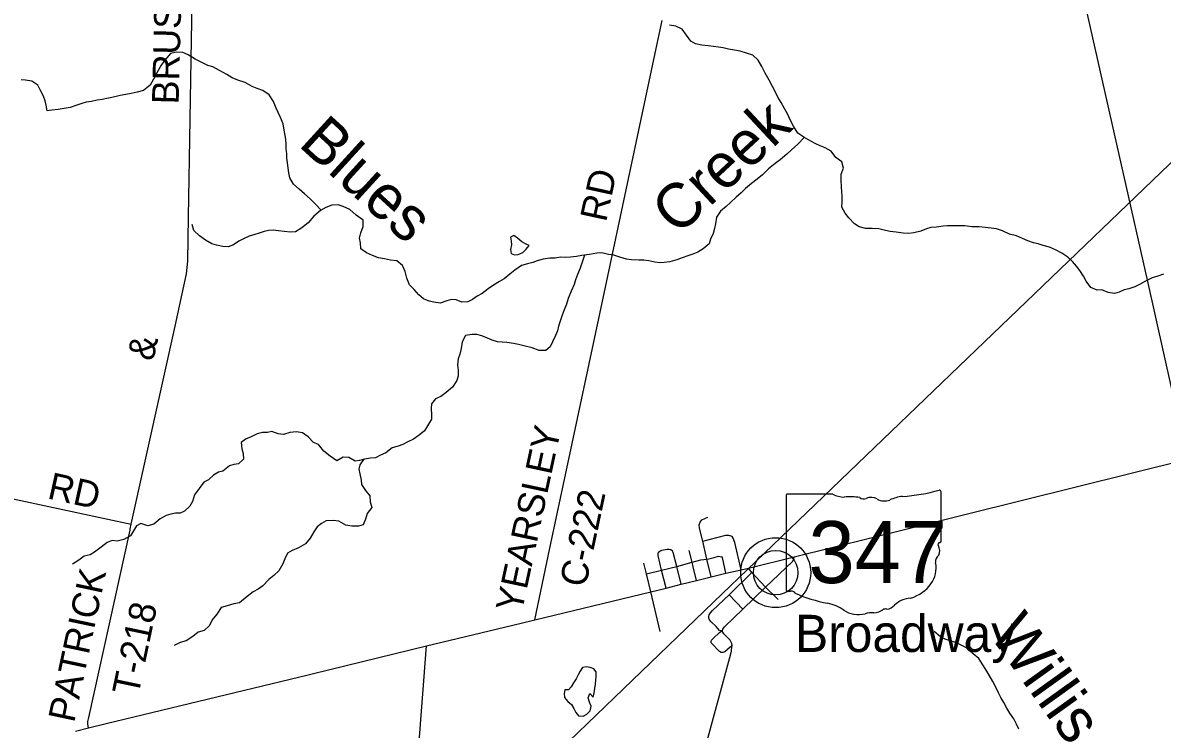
# Model space of a CAD drawing. Extents: x 0 to 34, y 0 to 22.
# Drawn here: x 5.454 to 6.665, y 16.008 to 16.759 of the extents above; entities that cross this region are included whole.
import ezdxf

# ---------------------------------------------------------------- set-up
doc = ezdxf.new("R2010")
doc.units = 0
for name, color, linetype in [('GM_X_County_Road', 7, 'Continuous'), ('GM_X_County_Road_Text', 7, 'Continuous'), ('GM_X_Minor_Lake', 7, 'Continuous'), ('GM_X_Minor_River', 7, 'Continuous'), ('GM_X_Minor_River_Text', 7, 'Continuous'), ('GM_X_Rail_Line', 7, 'Continuous'), ('GM_X_State_Location', 7, 'Continuous'), ('GM_X_State_Route', 7, 'Continuous'), ('GM_X_State_Shield', 7, 'Continuous'), ('GM_X_Township_Road', 7, 'Continuous'), ('GM_X_Township_Road_Text', 7, 'Continuous'), ('GM_X_Unincorporated', 7, 'Continuous'), ('GM_X_Unincorporated_Location', 7, 'Continuous'), ('GM_X_Unincorporated_Text', 7, 'Continuous')]:
    doc.layers.add(name, color=color, linetype=linetype)

msp = doc.modelspace()

# ---------------------------------------------------------------- linework, layer by layer
at = {"layer": 'GM_X_County_Road'}
for points in [[(5.9984, 16.124), (6.0142, 16.2003), (6.0675, 16.4491), (6.1282, 16.7363), (6.1336, 16.7611)], [(5.8932, 15.2994), (5.8674, 15.5635), (5.855, 15.6874), (5.8535, 15.703), (5.8532, 15.7217), (5.8547, 15.7358), (5.8584, 15.7865), (5.8627, 15.8321), (5.8703, 15.9318), (5.8747, 15.985), (5.8831, 16.0962)]]:
    msp.add_lwpolyline(points, dxfattribs=at)
at = {"layer": 'GM_X_Minor_Lake'}
for points in [[(5.989, 16.5234), (5.9883, 16.5237), (5.9846, 16.5258), (5.98, 16.5295), (5.9761, 16.5325), (5.9726, 16.5306), (5.9732, 16.5264), (5.9736, 16.5227), (5.9726, 16.5177), (5.9732, 16.5134)], [(5.9732, 16.5134), (5.9767, 16.512), (5.9807, 16.5124), (5.9855, 16.5145), (5.9893, 16.518), (5.9923, 16.522), (5.989, 16.5234)], [(6.058, 16.0303), (6.0584, 16.0322), (6.0565, 16.0364), (6.0551, 16.0411), (6.0568, 16.0455), (6.0602, 16.0417), (6.0613, 16.0462), (6.0627, 16.0555), (6.0631, 16.0599), (6.0635, 16.0641), (6.0635, 16.0686), (6.061, 16.072), (6.0573, 16.0732), (6.0531, 16.074), (6.0489, 16.0734), (6.0466, 16.0694), (6.0445, 16.0655), (6.0424, 16.0613), (6.0396, 16.0569), (6.0371, 16.0526), (6.0341, 16.0496), (6.0301, 16.0496)], [(6.0301, 16.0496), (6.0297, 16.0458), (6.03, 16.0414), (6.0334, 16.037), (6.0374, 16.0338), (6.0399, 16.0298), (6.0419, 16.0256), (6.0449, 16.022), (6.0497, 16.0216), (6.0538, 16.0237), (6.0573, 16.0273), (6.058, 16.0303)]]:
    msp.add_lwpolyline(points, dxfattribs=at)
at = {"layer": 'GM_X_Minor_River'}
for points in [[(6.3239, 16.5912), (6.3239, 16.5978), (6.3264, 16.6041), (6.3247, 16.6107), (6.3183, 16.6155), (6.3134, 16.6223), (6.3068, 16.6258), (6.3017, 16.6279), (6.2968, 16.63), (6.2917, 16.6328), (6.2843, 16.6369), (6.2779, 16.6414), (6.2732, 16.6488), (6.2696, 16.6555), (6.2668, 16.6618), (6.2641, 16.6669), (6.2602, 16.6739), (6.2566, 16.6794), (6.2538, 16.6857), (6.251, 16.691), (6.2474, 16.6977), (6.2433, 16.7049), (6.2397, 16.7121), (6.2357, 16.7188), (6.2301, 16.7243), (6.2233, 16.7262), (6.2166, 16.7283), (6.2104, 16.7295), (6.204, 16.7307), (6.1985, 16.732), (6.1934, 16.7328), (6.1881, 16.7334), (6.1824, 16.7342), (6.1758, 16.7349), (6.1691, 16.7363), (6.164, 16.7392), (6.1595, 16.7454), (6.1548, 16.7519), (6.1482, 16.7551), (6.1414, 16.7561)], [(5.7713, 16.5594), (5.7648, 16.5662), (5.7597, 16.5715), (5.7535, 16.5769), (5.748, 16.5818), (5.742, 16.5872), (5.738, 16.5938), (5.7369, 16.5991), (5.7354, 16.6098), (5.7349, 16.6147), (5.7347, 16.6194), (5.7343, 16.6251), (5.7342, 16.6304), (5.7336, 16.6369), (5.7321, 16.6443), (5.7308, 16.6513), (5.728, 16.6581), (5.7256, 16.6631), (5.7235, 16.668), (5.7207, 16.6749), (5.716, 16.6821), (5.7094, 16.6867), (5.7033, 16.6886), (5.6979, 16.6909), (5.6905, 16.6951), (5.6827, 16.6977), (5.6769, 16.7002), (5.671, 16.7035), (5.6634, 16.7079), (5.6561, 16.7117), (5.651, 16.7132), (5.6438, 16.7166), (5.6374, 16.7201), (5.63, 16.7246), (5.6245, 16.7269), (5.6177, 16.7273), (5.6114, 16.726), (5.6053, 16.7188), (5.6015, 16.7134), (5.5966, 16.7054), (5.5931, 16.6988), (5.5895, 16.6922), (5.5825, 16.6867), (5.5758, 16.6848), (5.5694, 16.6833), (5.5637, 16.6822), (5.5576, 16.6813), (5.5521, 16.6799), (5.5385, 16.677), (5.5334, 16.6764), (5.5273, 16.6751), (5.5218, 16.6742), (5.5171, 16.6728), (5.5106, 16.6706), (5.5047, 16.6687), (5.4981, 16.6674), (5.4919, 16.6665), (5.485, 16.6657), (5.4803, 16.665), (5.4792, 16.6709), (5.4781, 16.6756), (5.4764, 16.6806), (5.4728, 16.6874), (5.4704, 16.6923), (5.4638, 16.6967), (5.4573, 16.6975), (5.4524, 16.6979)], [(6.2846, 16.6367), (6.2778, 16.6297), (6.271, 16.6236), (6.2662, 16.6189), (6.2592, 16.6131), (6.2539, 16.6089), (6.2467, 16.6032), (6.2402, 16.597), (6.2345, 16.5925), (6.2286, 16.5879), (6.2223, 16.5825), (6.2176, 16.5777), (6.2123, 16.5734), (6.2064, 16.5677), (6.2016, 16.5634), (6.1955, 16.5583), (6.1915, 16.552), (6.1905, 16.5448), (6.1892, 16.5399), (6.1877, 16.5348), (6.1852, 16.5285), (6.1835, 16.5238), (6.1774, 16.5183), (6.1717, 16.5149), (6.1662, 16.5127), (6.1609, 16.5108), (6.155, 16.5087), (6.1493, 16.5065), (6.1419, 16.5046), (6.1358, 16.5037), (6.1311, 16.5035), (6.126, 16.5041), (6.1194, 16.5056), (6.1141, 16.5062), (6.1088, 16.5062), (6.1012, 16.5068), (6.0957, 16.5074), (6.0887, 16.5095), (6.0823, 16.5115), (6.0768, 16.5124), (6.0696, 16.514), (6.0643, 16.5136), (6.0565, 16.5123), (6.0485, 16.5114), (6.0425, 16.5101), (6.0362, 16.5095), (6.0311, 16.5092), (6.0258, 16.5094), (6.0199, 16.5085), (6.0144, 16.5085), (6.0072, 16.5074), (6.001, 16.5055), (5.9962, 16.5038), (5.9905, 16.5025), (5.9841, 16.5006), (5.9771, 16.4957), (5.9719, 16.4915), (5.9658, 16.4864), (5.9607, 16.4836), (5.9545, 16.4797), (5.9489, 16.4759), (5.9425, 16.471), (5.9372, 16.468), (5.932, 16.4644), (5.9271, 16.4621), (5.9207, 16.4616), (5.9148, 16.4641), (5.9099, 16.4644), (5.905, 16.4631), (5.8979, 16.4607), (5.8911, 16.4615), (5.8862, 16.4628), (5.8801, 16.4653), (5.8752, 16.4695), (5.87, 16.4752), (5.8651, 16.4802), (5.8624, 16.487), (5.8607, 16.4942), (5.8579, 16.5007), (5.8519, 16.5056), (5.8451, 16.5064), (5.8385, 16.5076), (5.8322, 16.5087), (5.8258, 16.5112), (5.8195, 16.5139), (5.8135, 16.5185), (5.8131, 16.5247), (5.8122, 16.5296), (5.8136, 16.5355), (5.816, 16.5422), (5.8161, 16.5488), (5.8087, 16.5541), (5.8017, 16.56), (5.7947, 16.5635), (5.7894, 16.5652), (5.7828, 16.5646), (5.7762, 16.5624), (5.7706, 16.559), (5.7636, 16.5529), (5.7575, 16.5461), (5.7507, 16.5407)], [(6.6664, 16.4915), (6.6603, 16.4894), (6.6544, 16.4875), (6.6474, 16.4838), (6.6408, 16.4804), (6.636, 16.4779), (6.6296, 16.4757), (6.6246, 16.4746), (6.6193, 16.4723), (6.6142, 16.471), (6.6076, 16.472), (6.601, 16.4748), (6.5958, 16.4745), (6.5892, 16.4774), (6.5843, 16.484), (6.5815, 16.4893), (6.5775, 16.4952), (6.5738, 16.5), (6.5698, 16.5047), (6.5649, 16.5093), (6.5585, 16.5137), (6.5517, 16.5171), (6.5452, 16.52), (6.5384, 16.5219), (6.5331, 16.5235), (6.5282, 16.5246), (6.5224, 16.5269), (6.5167, 16.5292), (6.5102, 16.5321), (6.5027, 16.534), (6.4953, 16.5374), (6.4889, 16.5396), (6.4834, 16.5403), (6.4768, 16.5411), (6.4701, 16.5417), (6.4627, 16.5417), (6.4552, 16.5427), (6.437, 16.5428), (6.4321, 16.5424), (6.4252, 16.5415), (6.4192, 16.541), (6.4144, 16.5396), (6.4087, 16.5372), (6.401, 16.5355), (6.3958, 16.5346), (6.3896, 16.535), (6.3824, 16.5362), (6.376, 16.5366), (6.3709, 16.5377), (6.3638, 16.5395), (6.3567, 16.5399), (6.3496, 16.5399), (6.343, 16.5418), (6.3379, 16.5449), (6.3321, 16.5513), (6.3283, 16.5563), (6.3247, 16.5625), (6.3248, 16.5686), (6.325, 16.5739), (6.3246, 16.579), (6.3241, 16.5844), (6.3239, 16.5912)], [(5.7507, 16.5407), (5.744, 16.5365), (5.7389, 16.536), (5.7319, 16.5369), (5.7261, 16.5375), (5.7204, 16.5381), (5.7154, 16.5377), (5.7107, 16.5366), (5.7056, 16.5351), (5.7008, 16.5334), (5.695, 16.5319), (5.6895, 16.5293), (5.684, 16.5263), (5.6781, 16.5225), (5.6726, 16.5204), (5.6669, 16.5208), (5.6603, 16.5222), (5.6552, 16.5235), (5.6483, 16.5277), (5.6419, 16.5321), (5.6361, 16.5378), (5.6344, 16.5441)], [(6.0513, 16.5117), (6.0485, 16.503), (6.0464, 16.4979), (6.0437, 16.4911), (6.0416, 16.4854), (6.0401, 16.4803), (6.037, 16.4733), (6.0338, 16.4655), (6.0319, 16.4595), (6.0296, 16.4534), (6.0273, 16.4477), (6.0255, 16.4424), (6.0236, 16.4362), (6.0223, 16.4312), (6.0205, 16.4263), (6.0173, 16.4193), (6.0146, 16.414), (6.0099, 16.4104), (6.0031, 16.4101), (5.9957, 16.4131), (5.9868, 16.4151), (5.9811, 16.4166), (5.9756, 16.4178), (5.9688, 16.4189), (5.9637, 16.4191), (5.9586, 16.4195), (5.9529, 16.4212), (5.948, 16.4232), (5.9419, 16.426), (5.9366, 16.4274), (5.9315, 16.4272), (5.9247, 16.4263), (5.9211, 16.4193), (5.9201, 16.4124), (5.9186, 16.4062), (5.917, 16.4015), (5.9162, 16.395), (5.9168, 16.3895), (5.9168, 16.3834), (5.9156, 16.3783), (5.9108, 16.3713), (5.9042, 16.3656), (5.8985, 16.3615), (5.8928, 16.3589), (5.8886, 16.3536), (5.8882, 16.3486), (5.8886, 16.342), (5.8886, 16.3371), (5.8845, 16.3301), (5.8811, 16.3248), (5.8754, 16.3202), (5.8695, 16.3159), (5.8636, 16.3131), (5.8583, 16.3102), (5.8532, 16.3085), (5.8468, 16.3067), (5.8399, 16.3016), (5.8344, 16.2991), (5.8291, 16.2963), (5.8238, 16.2957), (5.8174, 16.2946), (5.8122, 16.2935), (5.8075, 16.2926), (5.8009, 16.2966), (5.7948, 16.297), (5.788, 16.2928), (5.7808, 16.2978), (5.7742, 16.3031), (5.7684, 16.3103), (5.7633, 16.3124), (5.7576, 16.3185), (5.7515, 16.3229), (5.7453, 16.3239), (5.7381, 16.3231), (5.7313, 16.3211), (5.7256, 16.3215), (5.719, 16.324), (5.7142, 16.323), (5.7091, 16.323), (5.7032, 16.3217), (5.6964, 16.3182), (5.6917, 16.3165), (5.6863, 16.3123), (5.6869, 16.3059), (5.6886, 16.3009), (5.6889, 16.2947), (5.6834, 16.2899), (5.6787, 16.2892), (5.6739, 16.2877), (5.6669, 16.282), (5.6622, 16.2809), (5.657, 16.2777), (5.6515, 16.2728), (5.6468, 16.2703), (5.6418, 16.2635), (5.6367, 16.2567), (5.6346, 16.2497), (5.6319, 16.2448), (5.6262, 16.2395), (5.6215, 16.2372), (5.6165, 16.2372)], [(5.8162, 16.2944), (5.8124, 16.2888), (5.8114, 16.284), (5.8126, 16.2793), (5.8139, 16.2726), (5.8142, 16.2679), (5.8184, 16.2614), (5.8229, 16.2557), (5.8234, 16.2495), (5.8251, 16.2434), (5.8204, 16.2371), (5.8184, 16.2309), (5.816, 16.2248), (5.811, 16.2237), (5.804, 16.2235), (5.7974, 16.2247), (5.7902, 16.2287), (5.7841, 16.2297), (5.7768, 16.2291), (5.7718, 16.2265), (5.7671, 16.2229), (5.7636, 16.2176), (5.7596, 16.2108), (5.7547, 16.2047), (5.7473, 16.2006), (5.7405, 16.1978), (5.7357, 16.1947), (5.7328, 16.1887), (5.7306, 16.1834), (5.7264, 16.1762), (5.721, 16.1711), (5.7157, 16.1667), (5.7093, 16.1601), (5.7045, 16.1565), (5.6992, 16.1537), (5.6927, 16.1488), (5.6847, 16.142), (5.6785, 16.1409), (5.6715, 16.139), (5.6652, 16.1371), (5.6605, 16.1301), (5.6555, 16.1241), (5.6528, 16.118), (5.6469, 16.1127), (5.6407, 16.1108), (5.635, 16.1061), (5.628, 16.1016), (5.6217, 16.0999), (5.6152, 16.0967)], [(5.6165, 16.2372), (5.6116, 16.2363), (5.6067, 16.2348), (5.6004, 16.2314), (5.5936, 16.2256), (5.5873, 16.2239), (5.5799, 16.2264), (5.575, 16.2239), (5.5718, 16.2186), (5.5687, 16.2133), (5.5615, 16.2093), (5.5545, 16.2077), (5.5494, 16.2082), (5.5441, 16.206), (5.5376, 16.2013), (5.5306, 16.1958), (5.5258, 16.193), (5.5196, 16.1917), (5.5137, 16.1875), (5.507, 16.1832)], [(6.5128, 16.0076), (6.5103, 16.0129), (6.5073, 16.0186), (6.5032, 16.0249), (6.4998, 16.0299), (6.4968, 16.0361), (6.4934, 16.0413), (6.4909, 16.0462), (6.4877, 16.0532), (6.4849, 16.0584), (6.4785, 16.0694), (6.4744, 16.0762), (6.4702, 16.0829), (6.464, 16.088), (6.4572, 16.0941), (6.4521, 16.0968), (6.4459, 16.0997), (6.4409, 16.1012), (6.4345, 16.1035), (6.4296, 16.1058), (6.4228, 16.1115)]]:
    msp.add_lwpolyline(points, dxfattribs=at)
at = {"layer": 'GM_X_Rail_Line'}
msp.add_lwpolyline([(5.2658, 15.2105), (5.3357, 15.2914), (5.4094, 15.3777), (5.4899, 15.4707), (5.6406, 15.6155), (5.8342, 15.8017), (6.1881, 16.1426), (6.4582, 16.4022), (6.7352, 16.6681), (7.0136, 16.9364), (7.2435, 17.1561), (7.4421, 17.3509), (7.6263, 17.5265), (7.9296, 17.8183), (8.0773, 17.9623), (8.4366, 18.3089), (8.7009, 18.5622), (8.9, 18.7553)], dxfattribs=at)
at = {"layer": 'GM_X_State_Route'}
for p, q in [((6.3968, 16.2213), (6.6919, 16.2947)), ((5.8831, 16.0962), (5.9839, 16.1205))]:
    msp.add_line(p, q, dxfattribs=at)
for points in [[(6.866, 15.5217), (6.7711, 15.9427), (6.7648, 15.9704), (6.753, 16.0241), (6.743, 16.0689), (6.7354, 16.1024), (6.7219, 16.1619), (6.7041, 16.2402), (6.6919, 16.2947), (6.6496, 16.4835), (6.5435, 16.9548), (6.5242, 17.0407), (6.5004, 17.1471), (6.493, 17.1792)], [(5.9839, 16.1205), (5.9984, 16.124), (6.1217, 16.1539), (6.1378, 16.1577), (6.1538, 16.1618), (6.1701, 16.1658), (6.1858, 16.1696), (6.2014, 16.1735), (6.2177, 16.1771), (6.2255, 16.1789), (6.2739, 16.1908), (6.3968, 16.2213)], [(5.5102, 16.0058), (5.5242, 16.0092), (5.5428, 16.0138), (5.6311, 16.035), (5.7576, 16.0655), (5.7633, 16.0669), (5.8831, 16.0962)]]:
    msp.add_lwpolyline(points, dxfattribs=at)
at = {"layer": 'GM_X_State_Shield'}
for p, q in [((6.4301, 16.2079), (6.4301, 16.2602)), ((6.2653, 16.256), (6.2653, 16.1559)), ((6.3151, 16.2577), (6.2669, 16.2577)), ((6.43, 16.2079), (6.4301, 16.2079))]:
    msp.add_line(p, q, dxfattribs=at)
for centre, major_axis, start_param, end_param in [((6.3714, 16.3941), (0.1748, 0), 4.814394, 5.042369), ((6.4282, 16.2604), (0.00183, 0), 6.141152, 7.989035), ((6.2672, 16.2562), (0.00191, 0), 1.712693, 3.28349), ((6.3266, 16.2693), (0.0185, 0), 4.042523, 4.731795), ((6.3328, 16.2015), (0.0665, 0), 1.404758, 1.657858), ((6.3479, 16.2567), (0.00534, 0), 3.836095, 5.185415), ((6.3557, 16.2452), (0.0111, 0), 0.950623, 2.079405), ((6.37, 16.261), (0.0134, 0), 4.081561, 5.145723), ((6.3936, 16.2272), (0.0352, 0), 1.699011, 2.107814), ((6.4296, 16.204), (0.00284, 0), 1.883978, 3.671073), ((6.4116, 16.1974), (0.017, 0), 5.934695, 6.695948), ((6.4281, 16.2077), (0.00196, 0), 5.05454, 6.418171), ((6.4366, 16.186), (0.0124, 0), 2.387724, 3.262537), ((6.3811, 16.1793), (0.0437, 0), 5.101752, 6.440018), ((6.2672, 16.1557), (0.00193, 0), 3.00124, 4.508301), ((6.2675, 16.166), (0.0147, 0), 4.665946, 4.897461), ((6.2705, 16.1502), (0.0053, 0), 0.519207, 1.627899), ((6.3374, 16.2401), (0.1262, 0), 4.195997, 4.488961), ((6.2998, 16.111), (0.0395, 0), 0.823519, 1.323587), ((6.3692, 16.1462), (0.0141, 0), 4.937069, 5.64225), ((6.3996, 16.1279), (0.0239, 0), 1.647645, 2.488434), ((6.3425, 16.1497), (0.0251, 0), 4.026481, 4.996735), ((6.3569, 16.1151), (0.0206, 0), 1.495662, 1.94098), ((6.3588, 16.1422), (0.0133, 0), 4.691044, 5.507374), ((6.3708, 16.1325), (0.00376, 0), 1.147584, 2.315152)]:
    msp.add_ellipse(centre, major_axis=major_axis, ratio=0.8, start_param=start_param, end_param=end_param, dxfattribs=at)
at = {"layer": 'GM_X_Township_Road'}
for p, q in [((6.1656, 16.1851), (6.1625, 16.1977)), ((6.1667, 16.1802), (6.1656, 16.1851)), ((6.1701, 16.1658), (6.1667, 16.1802)), ((6.1316, 16.1116), (6.1217, 16.1539)), ((6.2195, 16.1352), (6.2049, 16.1507))]:
    msp.add_line(p, q, dxfattribs=at)
for points in [[(5.5685, 16.2208), (5.5694, 16.2257), (5.6161, 16.4362), (5.6282, 16.4916), (5.6297, 16.5051), (5.6304, 16.5525), (5.6316, 16.6139), (5.6336, 16.7405), (5.6362, 16.8713)], [(5.02, 16.3446), (5.3446, 16.2737), (5.5694, 16.2257)], [(6.1858, 16.1696), (6.1813, 16.1885), (6.177, 16.2077), (6.1734, 16.2213), (6.1731, 16.2249), (6.1739, 16.2277), (6.176, 16.2304), (6.1822, 16.2331)], [(5.5242, 16.0092), (5.5235, 16.013), (5.5235, 16.0159), (5.5243, 16.0202), (5.5683, 16.2194), (5.5685, 16.2208)], [(6.177, 16.2077), (6.2012, 16.2138), (6.2042, 16.214), (6.2063, 16.2134)], [(6.2177, 16.1771), (6.2108, 16.2063), (6.2093, 16.2107), (6.2081, 16.2124), (6.2063, 16.2134)], [(6.1172, 16.1729), (6.133, 16.1769), (6.1491, 16.1808), (6.1656, 16.1851), (6.1748, 16.1877), (6.1813, 16.1885)], [(6.1378, 16.1577), (6.133, 16.1769), (6.1296, 16.1923), (6.1293, 16.1945), (6.1299, 16.1959)], [(6.1299, 16.1959), (6.1311, 16.197), (6.1334, 16.1979), (6.139, 16.1991), (6.1407, 16.1992), (6.1425, 16.1987)], [(6.1538, 16.1618), (6.1491, 16.1808), (6.1455, 16.1957), (6.1447, 16.1971), (6.1425, 16.1987)], [(6.1813, 16.1885), (6.1833, 16.1887), (6.189, 16.1903), (6.1937, 16.1916), (6.1966, 16.191)], [(6.2014, 16.1735), (6.1977, 16.1901), (6.1966, 16.191)], [(6.2075, 16.0921), (6.208, 16.0972), (6.2077, 16.0987), (6.2071, 16.1002), (6.2058, 16.1024), (6.1991, 16.1091), (6.1981, 16.1109), (6.1977, 16.1122), (6.198, 16.1139), (6.1998, 16.1167), (6.2195, 16.1352), (6.2436, 16.1587), (6.2722, 16.1861), (6.2737, 16.1883), (6.2739, 16.1908)], [(6.1217, 16.1539), (6.1172, 16.1729), (6.1141, 16.1843)], [(6.2571, 16.1457), (6.2436, 16.1587), (6.2288, 16.1744), (6.2255, 16.1789)], [(6.1977, 16.1122), (6.1947, 16.1128), (6.191, 16.1168), (6.1856, 16.122), (6.1841, 16.1241), (6.1834, 16.1257), (6.1833, 16.1275), (6.1837, 16.1292), (6.185, 16.1313), (6.1873, 16.1338), (6.2049, 16.1507), (6.2288, 16.1744)], [(6.208, 16.0972), (6.2059, 16.095), (6.2004, 16.09), (6.1981, 16.0892), (6.1963, 16.0894), (6.1945, 16.0904), (6.1859, 16.0996), (6.1857, 16.1011), (6.1862, 16.1023), (6.1878, 16.1041), (6.1945, 16.1105), (6.1959, 16.1114), (6.1977, 16.1122)], [(6.2619, 15.3675), (6.2445, 15.5747), (6.2334, 15.724), (6.2316, 15.7419), (6.2303, 15.7488), (6.2278, 15.7592), (6.1897, 15.9077), (6.1773, 15.9565), (6.1759, 15.9621), (6.1753, 15.9661), (6.1754, 15.9704), (6.176, 15.9741), (6.1776, 15.9806), (6.1794, 15.9875), (6.2056, 16.0841), (6.2073, 16.0906), (6.2075, 16.0921)]]:
    msp.add_lwpolyline(points, dxfattribs=at)
at = {"layer": 'GM_X_Unincorporated'}
for radius in [0.0372, 0.0236]:
    msp.add_circle((6.2543, 16.1741), radius, dxfattribs=at)
at = {"layer": 'GM_X_Unincorporated_Location'}
msp.add_line((6.2543, 16.1741), (6.2543, 16.1741), dxfattribs=at)

# ---------------------------------------------------------------- texts
at = {"layer": 'GM_X_County_Road_Text'}
for s, rotation, p in [('RD', 77.735, (6.074, 16.5459)), ('YEARSLEY', 77.9145, (5.9844, 16.1305)), ('C-222', 78.0404, (6.0523, 16.1575))]:
    msp.add_text(s, height=0.02841, rotation=rotation, dxfattribs=at).set_placement(p)
at = {"layer": 'GM_X_Minor_River_Text'}
for s, height, rotation, p in [('Creek', 0.04735, 42.9218, (6.1503, 16.5312)), ('Blues', 0.04734, 317.6558, (5.746, 16.6285)), ('Willis', 0.04735, 305.6442, (6.4802, 16.1088))]:
    msp.add_text(s, height=height, rotation=rotation, dxfattribs=at).set_placement(p)
at = {"layer": 'GM_X_State_Location'}
msp.add_text('347', height=0.0000947, rotation=0, dxfattribs=at).set_placement((6.3124, 16.1924))
for s in ['s', 'r']:
    msp.add_text(s, height=0.0000947, dxfattribs=at).set_placement((6.3458, 16.1993))
at = {"layer": 'GM_X_State_Shield'}
msp.add_text('347', height=0.06592, dxfattribs=at).set_placement((6.2892, 16.163))
at = {"layer": 'GM_X_Township_Road_Text'}
for s, height, rotation, p in [('BRUSH', 0.02841, 88.5576, (5.6199, 16.6717)), ('&', 0.0284, 77.3777, (5.5927, 16.3981)), ('RD', 0.02841, 347.524, (5.4794, 16.2532)), ('PATRICK', 0.02841, 78.029, (5.5089, 16.0138)), ('T-218', 0.02841, 78.1403, (5.5769, 16.0422))]:
    msp.add_text(s, height=height, rotation=rotation, dxfattribs=at).set_placement(p)
at = {"layer": 'GM_X_Unincorporated_Text'}
msp.add_text('Broadway', height=0.03949, rotation=0, dxfattribs=at).set_placement((6.2749, 16.0898))

doc.saveas('drawing.dxf')
